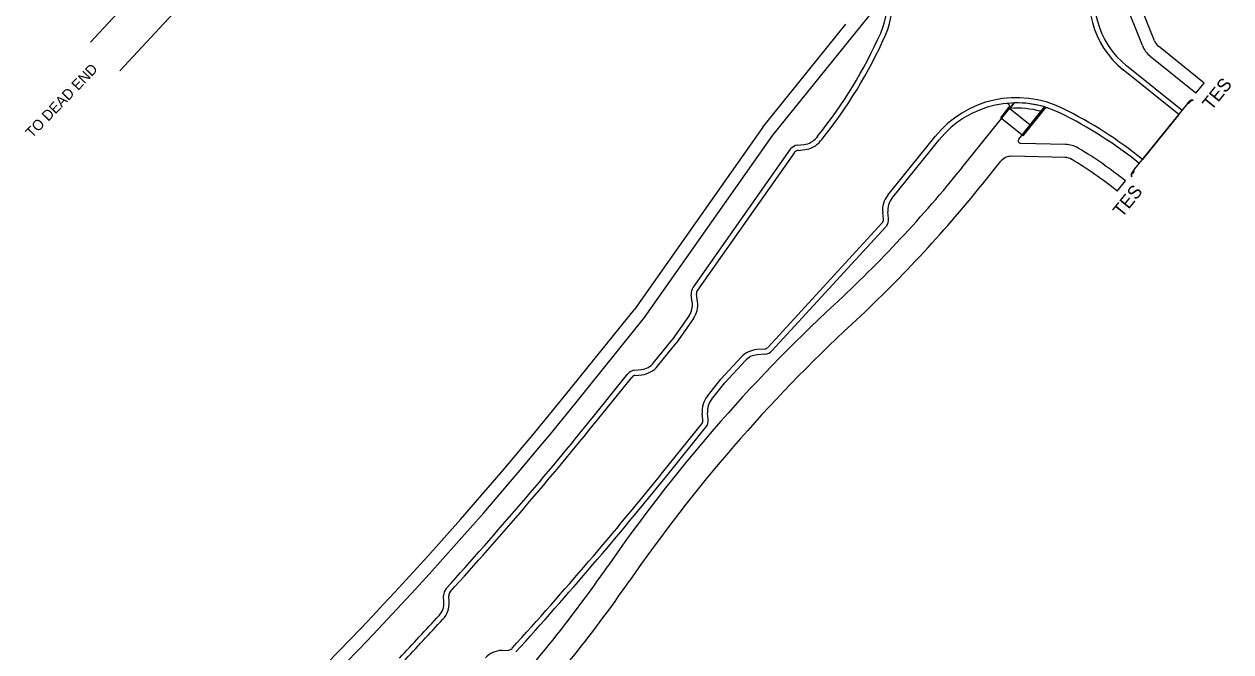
# Model space of a CAD drawing. Extents: x 1487693 to 1489338, y 497936 to 499734.
# Drawn here: x 1488341.6 to 1488802.7, y 498835.3 to 499075 of the extents above; entities that cross this region are included whole.
import ezdxf

# ---------------------------------------------------------------- set-up
doc = ezdxf.new("R2010")
doc.units = 0
for name, color, linetype in [('Exist Roads EOP', 7, 'Continuous'), ('Exist Roads EOP Text', 7, 'Continuous'), ('Pattern 5', 7, 'Continuous'), ('Prop Conc 1ft 6in Curb and Gutter', 7, 'Continuous'), ('Prop Conc 2ft 6in Curb and Gutter', 7, 'Continuous'), ('Prop Conc 4in Sidewalk', 7, 'Continuous'), ('Prop EOT', 7, 'Continuous'), ('Prop Guardrail', 7, 'Continuous'), ('Prop Guardrail Anchor Unit CELL', 7, 'Continuous')]:
    doc.layers.add(name, color=color, linetype=linetype)

msp = doc.modelspace()

# ---------------------------------------------------------------- linework, layer by layer
at = {"layer": 'Exist Roads EOP'}
for points in [[(1488559.94, 499273.47), (1488551.23, 499261.94), (1488527.57, 499236.62), (1488509.57, 499218.46), (1488492.8, 499200.86), (1488473.58, 499181.74), (1488457.57, 499165.28), (1488439.63, 499146.96), (1488422.23, 499128.57), (1488403.81, 499108.39), (1488389.02, 499091.96), (1488366.93, 499068.16)], [(1488574.77, 499260.93), (1488563.13, 499248.19), (1488539.56, 499225.13), (1488520.46, 499206.56), (1488504.08, 499189.42), (1488484.54, 499170.35), (1488469.06, 499154.33), (1488450.55, 499135.83), (1488433.88, 499117.95), (1488414.86, 499097.38), (1488400.17, 499080.83), (1488378.14, 499057.25)]]:
    msp.add_lwpolyline(points, dxfattribs=at)
at = {"layer": 'Pattern 5'}
for p, q in [((1488719.96, 499044.95), (1488718.28, 499042.87)), ((1488730.19, 499041.71), (1488731.56, 499043.4))]:
    msp.add_line(p, q, dxfattribs=at)
for radius, start, end in [(36, 74.8676, 94.0027), (38, 73.5472, 91.2616)]:
    msp.add_arc((1488720.8, 499006.96), radius, start, end, dxfattribs=at)
at = {"layer": 'Prop Conc 1ft 6in Curb and Gutter'}
for p, q in [((1488714.75, 499039.29), (1488717.86, 499043.15)), ((1488723.32, 499032.39), (1488731.64, 499042.71)), ((1488715.14, 499038.98), (1488714.75, 499039.29)), ((1488722.93, 499032.7), (1488723.32, 499032.39))]:
    msp.add_line(p, q, dxfattribs=at)
for centre, start, end in [((1488717.08, 499043.77), 321.1156, 95.7599), ((1488732.42, 499042.09), 71.6856, 141.1156)]:
    msp.add_arc(centre, 1, start, end, dxfattribs=at)
at = {"layer": 'Prop Conc 2ft 6in Curb and Gutter'}
for p, q in [((1488784.04, 499042.03), (1488762.85, 499059.11)), ((1488782.79, 499040.47), (1488784.04, 499042.03)), ((1488637.16, 499028.83), (1488639.66, 499029.1)), ((1488644.81, 499032.22), (1488644.37, 499031.66)), ((1488673.17, 499008.44), (1488691.22, 499030.81)), ((1488634.37, 499027.23), (1488597.22, 498974.53)), ((1488634.37, 499027.23), (1488634.48, 499027.36)), ((1488767.72, 499021.79), (1488768.98, 499023.34)), ((1488671.93, 499000.8), (1488671.66, 499003.3)), ((1488627.33, 498950.25), (1488670.91, 498997.68)), ((1488670.91, 498997.68), (1488671.06, 498997.86)), ((1488596.93, 498968.75), (1488596.52, 498971.68)), ((1488595.72, 498963.75), (1488589.18, 498954.47)), ((1488582.11, 498945.7), (1488589.18, 498954.47)), ((1488609.38, 498938.1), (1488617.1, 498946.5)), ((1488624.68, 498948.97), (1488621.73, 498948.75)), ((1488559.11, 498925.15), (1488572.22, 498941.4)), ((1488574.9, 498942.86), (1488577.4, 498943.13)), ((1488604.23, 498931.71), (1488609.38, 498938.1)), ((1488602.99, 498924.07), (1488602.72, 498926.57)), ((1488587.14, 498902.55), (1488602.12, 498921.13)), ((1488502.01, 498854.22), (1488501.88, 498856.66))]:
    msp.add_line(p, q, dxfattribs=at)
for centre, radius, start, end in [((1488643.32, 499083.01), 28, 336.027, 47.2261), ((1488783.57, 499084.8), 33, 159.3105, 231.1156), ((1488506.26, 499143.96), 178, 321.1156, 336.027), ((1488720.8, 499006.96), 38, 63.6938, 141.1156), ((1488665.4, 498894.91), 163, 51.1156, 63.6938), ((1488637.59, 499024.85), 4, 96.1156, 141.1156), ((1488638.92, 499036.06), 7, 276.1156, 321.1156), ((1488678.62, 499004.04), 7, 141.1156, 186.1156), ((1488667.95, 499000.37), 4, 321.1156, 6.1156), ((1488600.49, 498972.23), 4, 144.8179, 187.9107), ((1488590, 498967.78), 7, 324.8179, 7.9107), ((1488624.38, 498952.96), 4, 274.3206, 317.4134), ((1488576.66, 498950.09), 7, 276.1156, 321.1156), ((1488622.26, 498941.77), 7, 94.3206, 137.4134), ((1488575.33, 498938.89), 4, 96.1156, 141.1156), ((1488609.68, 498927.32), 7, 141.1156, 186.1156), ((1487424.96, 499839.79), 1457, 317.71824, 321.11565), ((1488599.01, 498923.65), 4, 321.1156, 6.1156), ((1487424.96, 499839.79), 1493, 317.71734, 321.11565), ((1488505.88, 498856.86), 4, 137.7182, 182.8519), ((1488495.01, 498853.87), 7, 317.3435, 2.8519), ((1487424.96, 499839.79), 1462, 316.47396, 317.34346)]:
    msp.add_arc(centre, radius, start, end, dxfattribs=at)
at = {"layer": 'Prop Conc 4in Sidewalk'}
for p, q in [((1488773.56, 499068.66), (1488765.37, 499089.29)), ((1488768.91, 499066.82), (1488761.64, 499085.14)), ((1488627.75, 499032.57), (1488666.32, 499080.39)), ((1488623.86, 499035.7), (1488655.57, 499075.03)), ((1488792.52, 499052.53), (1488775.06, 499066.61)), ((1488789.38, 499048.64), (1488771.93, 499062.72)), ((1488789.38, 499048.64), (1488792.52, 499052.53)), ((1488699.97, 499020.17), (1488719.96, 499044.95)), ((1488718.28, 499042.87), (1488726.07, 499036.59)), ((1488721.65, 499031.12), (1488731.56, 499043.4)), ((1488715.14, 499038.98), (1488722.93, 499032.7)), ((1488623.86, 499035.7), (1488574.78, 498966.09)), ((1488578.67, 498962.95), (1488627.75, 499032.57)), ((1488739.48, 499029.1), (1488722.4, 499029.49)), ((1488739.37, 499024.1), (1488718.87, 499024.57)), ((1488707.76, 499013.89), (1488714.87, 499022.71)), ((1488759.25, 499011.28), (1488762.39, 499015.17)), ((1488548.61, 498933.63), (1488574.78, 498966.09)), ((1488552.5, 498930.49), (1488578.67, 498962.95))]:
    msp.add_line(p, q, dxfattribs=at)
for centre, radius, start, end in [((1488778.2, 499070.5), 10, 201.6281, 231.1156), ((1488778.2, 499070.5), 5, 201.6281, 231.1156), ((1488720.8, 499006.96), 36, 74.8588, 94.0027), ((1488722.43, 499030.49), 1, 141.1156, 268.6989), ((1488739.26, 499019.1), 10, 59.261, 88.6989), ((1488718.76, 499019.57), 5, 88.6989, 141.1156), ((1488739.26, 499019.1), 5, 59.261, 88.6989), ((1488665.4, 498894.91), 149.5, 51.1156, 59.261), ((1488665.4, 498894.91), 154.5, 51.1156, 59.261), ((1488314.66, 499330.9), 495, 312.8235, 321.1156), ((1488314.66, 499330.9), 505, 312.8235, 321.1156), ((1489062.37, 498524.11), 605, 132.82346, 145.35373), ((1489062.37, 498524.11), 595, 132.82346, 145.35373), ((1487424.96, 499839.79), 1443.5, 305.25533, 321.11565), ((1487424.96, 499839.79), 1448.5, 311.19416, 321.11565), ((1488157.43, 499149.47), 495, 316.6966, 325.3537), ((1488157.43, 499149.47), 505, 316.6966, 325.3537)]:
    msp.add_arc(centre, radius, start, end, dxfattribs=at)
at = {"layer": 'Prop EOT'}
for p, q in [((1488782.79, 499040.47), (1488761.6, 499057.56)), ((1488782.79, 499040.47), (1488768.98, 499023.34)), ((1488646.37, 499030.96), (1488645.92, 499030.41)), ((1488671.61, 499009.69), (1488689.66, 499032.07)), ((1488635.93, 499025.97), (1488598.85, 498973.38)), ((1488635.93, 499025.97), (1488636.03, 499026.11)), ((1488637.38, 499026.84), (1488639.88, 499027.11)), ((1488669.94, 499000.58), (1488669.67, 499003.08)), ((1488625.85, 498951.61), (1488669.4, 498998.98)), ((1488669.4, 498998.98), (1488669.5, 498999.11)), ((1488598.91, 498969.02), (1488598.5, 498971.95)), ((1488597.35, 498962.6), (1488590.74, 498953.22)), ((1488583.66, 498944.44), (1488590.74, 498953.22)), ((1488624.53, 498950.96), (1488621.58, 498950.74)), ((1488607.87, 498939.41), (1488615.63, 498947.86)), ((1488560.67, 498923.9), (1488573.77, 498940.14)), ((1488575.12, 498940.88), (1488577.62, 498941.14)), ((1488602.67, 498932.97), (1488607.87, 498939.41)), ((1488601, 498923.86), (1488600.73, 498926.36)), ((1488585.58, 498903.81), (1488600.57, 498922.39)), ((1488504, 498854.32), (1488503.88, 498856.76)), ((1488524.09, 498835.88), (1488526.68, 498836.01))]:
    msp.add_line(p, q, dxfattribs=at)
for centre, radius, start, end in [((1488643.32, 499083.01), 30, 336.027, 47.2261), ((1488783.57, 499084.8), 35, 159.3105, 231.1156), ((1488506.26, 499143.96), 180, 321.1156, 336.027), ((1488720.8, 499006.96), 40, 63.6938, 141.1156), ((1488665.4, 498894.91), 165, 51.1156, 63.6938), ((1488638.92, 499036.06), 9, 276.1156, 321.1156), ((1488637.59, 499024.85), 2, 96.1156, 141.1156), ((1488678.62, 499004.04), 9, 141.1156, 186.1156), ((1488667.95, 499000.37), 2, 321.1156, 6.1156), ((1488600.49, 498972.23), 2, 144.8179, 187.9107), ((1488590, 498967.78), 9, 324.8179, 7.9107), ((1488622.26, 498941.77), 9, 94.3206, 137.4134), ((1488624.38, 498952.96), 2, 274.3206, 317.4134), ((1488575.33, 498938.89), 2, 96.1156, 141.1156), ((1488576.66, 498950.09), 9, 276.1156, 321.1156), ((1488609.68, 498927.32), 9, 141.1156, 186.1156), ((1487424.96, 499839.79), 1459, 317.71824, 321.11565), ((1488599.01, 498923.65), 2, 321.1156, 6.1156), ((1487424.96, 499839.79), 1491, 317.71734, 321.11565), ((1488505.88, 498856.86), 2, 137.7182, 182.8519), ((1488495.01, 498853.87), 9, 317.3435, 2.8519), ((1487424.96, 499839.79), 1464, 316.47396, 317.34346), ((1488524.54, 498826.89), 9, 92.8495, 137.3496), ((1488526.58, 498838), 2, 272.8495, 317.7173)]:
    msp.add_arc(centre, radius, start, end, dxfattribs=at)
at = {"layer": 'Prop Guardrail'}
msp.add_line((1488765.55, 499019.09), (1488786.21, 499044.72), dxfattribs=at)
at = {"layer": 'Prop Guardrail Anchor Unit CELL'}
for p, q in [((1488786.21, 499044.72), (1488786.92, 499045.59)), ((1488786.21, 499044.72), (1488786.43, 499044.54)), ((1488786.43, 499044.54), (1488787.14, 499045.42)), ((1488765.55, 499019.09), (1488764.85, 499018.22)), ((1488765.77, 499018.92), (1488765.06, 499018.04)), ((1488765.55, 499019.09), (1488765.77, 499018.92))]:
    msp.add_line(p, q, dxfattribs=at)
for centre, radius, start, end in [((1488787.88, 499044.77), 1.27, 69.0507, 139.4447), ((1488788.33, 499044.35), 1.6, 89.9907, 138.2982), ((1488765.85, 499017.45), 1.27, 142.7866, 213.1806), ((1488766.36, 499017.1), 1.6, 143.9331, 192.2406)]:
    msp.add_arc(centre, radius, start, end, dxfattribs=at)

# ---------------------------------------------------------------- texts
at = {"layer": 'Exist Roads EOP Text'}
msp.add_text('TO DEAD END', height=4, rotation=45.9764, dxfattribs=at).set_placement((1488344.63, 499031.29))
at = {"layer": 'Prop Guardrail Anchor Unit CELL'}
for p in [(1488795.27, 499041.79), (1488761.09, 499000.93)]:
    msp.add_text('TES', height=5, rotation=51.1156, dxfattribs=at).set_placement(p)

doc.saveas('drawing.dxf')
